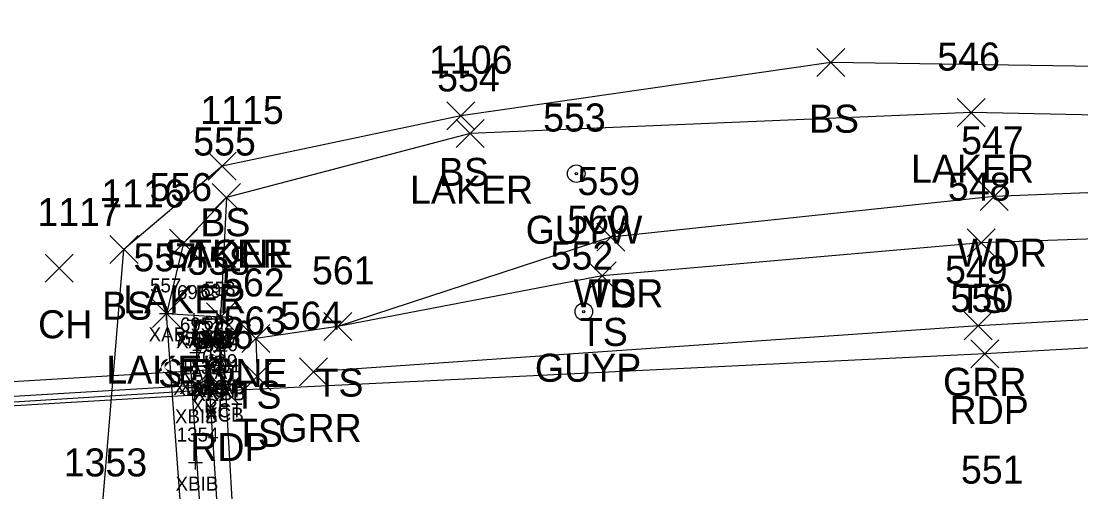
# Model space of a CAD drawing. Extents: x 1715662 to 1717487, y 887396 to 890004.
# Drawn here: x 1717162.5 to 1717238, y 888253.5 to 888287.1 of the extents above; entities that cross this region are included whole.
import ezdxf

# ---------------------------------------------------------------- set-up
doc = ezdxf.new("R2010")
doc.units = 0
for name, color, linetype in [('B_A', 7, 'Continuous'), ('B_I', 7, 'Continuous'), ('B_TIC', 7, 'Continuous'), ('BDC', 7, 'Continuous'), ('BF', 7, 'Continuous'), ('BR', 7, 'Continuous'), ('BSE', 7, 'Continuous'), ('BSUBM', 7, 'Continuous'), ('L_A', 7, 'Continuous'), ('L_I', 7, 'Continuous'), ('L_TIC', 7, 'Continuous'), ('LASF', 7, 'Continuous'), ('LAWA', 7, 'Continuous'), ('LAWE', 7, 'Continuous'), ('LELB', 7, 'Continuous'), ('P_A', 7, 'Continuous'), ('P_I', 7, 'Continuous'), ('P_TIC', 7, 'Continuous'), ('PET', 7, 'Continuous'), ('R_A', 7, 'Continuous'), ('R_I', 7, 'Continuous'), ('R_TIC', 7, 'Continuous'), ('RGR', 7, 'Continuous'), ('U_A', 7, 'Continuous'), ('U_I', 7, 'Continuous'), ('UPGW', 7, 'Continuous')]:
    doc.layers.add(name, color=color, linetype=linetype)

msp = doc.modelspace()

# ---------------------------------------------------------------- linework, layer by layer
at = {"layer": 'B_TIC'}
for p, q in [((1717172.863, 888266.22), (1717172.939, 888266.22)), ((1717174.834, 888265.741), (1717174.91, 888265.741)), ((1717176.473, 888265.837), (1717176.548, 888265.837)), ((1717176.717, 888265.975), (1717176.792, 888265.975)), ((1717175.018, 888263.43), (1717175.094, 888263.43)), ((1717176.687, 888263.555), (1717176.762, 888263.555)), ((1717174.599, 888262.408), (1717174.675, 888262.408)), ((1717175.062, 888262.468), (1717175.137, 888262.468)), ((1717175.803, 888262.49), (1717175.879, 888262.49)), ((1717176.726, 888262.528), (1717176.802, 888262.528)), ((1717177.084, 888262.456), (1717177.16, 888262.456)), ((1717176.001, 888261.982), (1717176.076, 888261.982)), ((1717176.593, 888262.234), (1717176.668, 888262.234)), ((1717176.593, 888262.234), (1717176.668, 888262.234)), ((1717176.979, 888262.024), (1717177.055, 888262.024)), ((1717175.884, 888261.141), (1717175.959, 888261.141)), ((1717174.882, 888260.387), (1717174.958, 888260.387)), ((1717176.87, 888260.514), (1717176.945, 888260.514)), ((1717176.881, 888260.812), (1717176.956, 888260.812)), ((1717174.931, 888255.588), (1717175.006, 888255.588))]:
    msp.add_line(p, q, dxfattribs=at)
for points in [[(1717172.36, 888266.22), (1717173.36, 888266.22)], [(1717172.86, 888265.72), (1717172.86, 888266.72)], [(1717174.831, 888265.241), (1717174.831, 888266.241)], [(1717176.469, 888265.337), (1717176.469, 888266.337)], [(1717176.713, 888265.475), (1717176.713, 888266.475)], [(1717174.331, 888265.741), (1717175.331, 888265.741)], [(1717175.969, 888265.837), (1717176.969, 888265.837)], [(1717176.213, 888265.975), (1717177.213, 888265.975)], [(1717175.015, 888262.93), (1717175.015, 888263.93)], [(1717176.683, 888263.055), (1717176.683, 888264.055)], [(1717174.515, 888263.43), (1717175.515, 888263.43)], [(1717176.183, 888263.555), (1717177.183, 888263.555)], [(1717174.096, 888262.408), (1717175.096, 888262.408)], [(1717174.558, 888262.468), (1717175.558, 888262.468)], [(1717174.596, 888261.908), (1717174.596, 888262.908)], [(1717175.058, 888261.968), (1717175.058, 888262.968)], [(1717175.3, 888262.49), (1717176.3, 888262.49)], [(1717175.8, 888261.99), (1717175.8, 888262.99)], [(1717175.997, 888261.482), (1717175.997, 888262.482)], [(1717176.223, 888262.528), (1717177.223, 888262.528)], [(1717176.581, 888262.456), (1717177.581, 888262.456)], [(1717176.589, 888261.734), (1717176.589, 888262.734)], [(1717176.589, 888261.734), (1717176.589, 888262.734)], [(1717176.723, 888262.028), (1717176.723, 888263.028)], [(1717176.976, 888261.524), (1717176.976, 888262.524)], [(1717177.081, 888261.956), (1717177.081, 888262.956)], [(1717175.497, 888261.982), (1717176.497, 888261.982)], [(1717175.88, 888260.641), (1717175.88, 888261.641)], [(1717176.089, 888262.234), (1717177.089, 888262.234)], [(1717176.089, 888262.234), (1717177.089, 888262.234)], [(1717176.476, 888262.024), (1717177.476, 888262.024)], [(1717174.879, 888259.887), (1717174.879, 888260.887)], [(1717175.38, 888261.141), (1717176.38, 888261.141)], [(1717176.866, 888260.014), (1717176.866, 888261.014)], [(1717176.877, 888260.312), (1717176.877, 888261.312)], [(1717174.379, 888260.387), (1717175.379, 888260.387)], [(1717176.366, 888260.514), (1717177.366, 888260.514)], [(1717176.377, 888260.812), (1717177.377, 888260.812)], [(1717174.427, 888255.588), (1717175.427, 888255.588)], [(1717174.927, 888255.088), (1717174.927, 888256.088)]]:
    msp.add_lwpolyline(points, dxfattribs=at)
at = {"layer": 'BDC'}
for points in [[(1717176.589, 888262.234), (1717176.877, 888260.812), (1717116.829, 888257.088), (1717056.7, 888253.344), (1716997.03, 888249.858), (1716936.998, 888246.313), (1716877.496, 888242.928), (1716877.301, 888244.49)], [(1717176.976, 888262.024), (1717176.866, 888260.514), (1717116.827, 888256.946), (1717056.83, 888253.148), (1716997.002, 888249.663), (1716937.062, 888246.095), (1716877.423, 888242.56)]]:
    msp.add_lwpolyline(points, dxfattribs=at)
at = {"layer": 'BF'}
msp.add_lwpolyline([(1717176.589, 888262.234), (1717116.538, 888258.636), (1717056.61, 888254.944), (1716996.925, 888251.433), (1716937.102, 888247.945), (1716877.301, 888244.49)], dxfattribs=at)
at = {"layer": 'BR'}
msp.add_lwpolyline([(1717175.997, 888261.982), (1717175.88, 888261.141), (1717117.062, 888257.612), (1717056.557, 888253.997), (1716997.021, 888250.409), (1716936.966, 888246.784), (1716878.141, 888243.386), (1716877.962, 888244.411)], dxfattribs=at)
at = {"layer": 'BSE'}
for points in [[(1717175.8, 888262.49), (1717174.596, 888262.408)], [(1717176.7, 888230.2), (1717174.596, 888262.408)], [(1717175.8, 888262.49), (1717177.89, 888230.3)]]:
    msp.add_lwpolyline(points, dxfattribs=at)
at = {"layer": 'BSUBM'}
for points in [[(1717172.86, 888266.22), (1717176.713, 888265.975), (1717177.081, 888262.456)], [(1717175.765, 888226.393), (1717172.86, 888266.22)], [(1717176.683, 888263.555), (1717176.723, 888262.528), (1717175.058, 888262.468), (1717175.015, 888263.43), (1717174.831, 888265.741), (1717176.469, 888265.837)], [(1717176.469, 888265.837), (1717176.683, 888263.555)]]:
    msp.add_lwpolyline(points, dxfattribs=at)
at = {"layer": 'L_TIC'}
for points in [[(1717219.203, 888283.101), (1717221.203, 888285.101)], [(1717221.203, 888283.101), (1717219.203, 888285.101)], [(1717192.827, 888279.308), (1717194.827, 888281.308)], [(1717194.827, 888279.308), (1717192.827, 888281.308)], [(1717229.209, 888279.531), (1717231.209, 888281.531)], [(1717231.209, 888279.531), (1717229.209, 888281.531)], [(1717193.5, 888278.043), (1717195.5, 888280.043)], [(1717195.5, 888278.043), (1717193.5, 888280.043)], [(1717175.82, 888275.721), (1717177.82, 888277.721)], [(1717177.82, 888275.721), (1717175.82, 888277.721)], [(1717176.118, 888273.475), (1717178.118, 888275.475)], [(1717178.118, 888273.475), (1717176.118, 888275.475)], [(1717176.118, 888273.475), (1717178.118, 888275.475)], [(1717178.118, 888273.475), (1717176.118, 888275.475)], [(1717230.85, 888273.551), (1717232.85, 888275.551)], [(1717232.85, 888273.551), (1717230.85, 888275.551)], [(1717173.059, 888270.227), (1717175.059, 888272.227)], [(1717175.059, 888270.227), (1717173.059, 888272.227)], [(1717203.517, 888270.654), (1717205.517, 888272.654)], [(1717205.517, 888270.654), (1717203.517, 888272.654)], [(1717203.517, 888270.654), (1717205.517, 888272.654)], [(1717205.517, 888270.654), (1717203.517, 888272.654)], [(1717229.913, 888270.259), (1717231.913, 888272.259)], [(1717231.913, 888270.259), (1717229.913, 888272.259)], [(1717168.821, 888269.772), (1717170.821, 888271.772)], [(1717170.821, 888269.772), (1717168.821, 888271.772)], [(1717164.209, 888268.447), (1717166.209, 888270.447)], [(1717166.209, 888268.447), (1717164.209, 888270.447)], [(1717202.911, 888267.903), (1717204.911, 888269.903)], [(1717204.911, 888267.903), (1717202.911, 888269.903)], [(1717171.86, 888265.22), (1717173.86, 888267.22)], [(1717173.86, 888265.22), (1717171.86, 888267.22)], [(1717175.713, 888264.975), (1717177.713, 888266.975)], [(1717177.713, 888264.975), (1717175.713, 888266.975)], [(1717184.063, 888264.292), (1717186.063, 888266.292)], [(1717186.063, 888264.292), (1717184.063, 888266.292)], [(1717184.063, 888264.292), (1717186.063, 888266.292)], [(1717186.063, 888264.292), (1717184.063, 888266.292)], [(1717178.223, 888263.43), (1717180.223, 888265.43)], [(1717180.223, 888263.43), (1717178.223, 888265.43)], [(1717178.323, 888260.717), (1717180.323, 888262.717)], [(1717180.323, 888260.717), (1717178.323, 888262.717)]]:
    msp.add_lwpolyline(points, dxfattribs=at)
at = {"layer": 'LASF'}
msp.add_lwpolyline([(1717177.118, 888274.475), (1717176.713, 888265.975)], dxfattribs=at)
at = {"layer": 'LAWA'}
msp.add_lwpolyline([(1717427.067, 888329.961), (1717424.149, 888313.244), (1717417.81, 888299.744), (1717405.976, 888286.015), (1717373.069, 888282.354), (1717318.582, 888277.997), (1717270.109, 888276.059), (1717231.85, 888274.551), (1717204.517, 888271.654)], dxfattribs=at)
at = {"layer": 'LAWE'}
msp.add_lwpolyline([(1717421.683, 888328.919), (1717420.886, 888312.991), (1717415.109, 888301.397), (1717401.413, 888289.205), (1717371.004, 888285.951), (1717321.686, 888282.443), (1717271.809, 888279.668), (1717230.209, 888280.531), (1717194.5, 888279.043), (1717177.118, 888274.475), (1717174.059, 888271.227), (1717172.86, 888266.22)], dxfattribs=at)
at = {"layer": 'LELB'}
for points in [[(1717397.436, 888368.91), (1717401.938, 888364.629), (1717406.066, 888347.478), (1717411.38, 888343.282), (1717409.785, 888309.959), (1717403.016, 888297.908), (1717392.211, 888290.651), (1717353.828, 888286.564), (1717306.03, 888285.644), (1717272.452, 888283.322), (1717220.203, 888284.101), (1717193.827, 888280.308), (1717176.82, 888276.721), (1717169.821, 888270.772)], [(1717414.269, 888287.03), (1717406.988, 888281.7), (1717373.99, 888277.877), (1717318.522, 888275.495), (1717269.658, 888272.606), (1717230.913, 888271.259), (1717203.911, 888268.903), (1717185.063, 888265.292), (1717179.223, 888264.43), (1717179.323, 888261.717)], [(1717204.517, 888271.654), (1717185.063, 888265.292)], [(1717168.218, 888251.599), (1717169.821, 888270.772)]]:
    msp.add_lwpolyline(points, dxfattribs=at)
at = {"layer": 'P_TIC'}
for points in [[(1717230.181, 888262.331), (1717232.181, 888264.331)], [(1717232.181, 888262.331), (1717230.181, 888264.331)], [(1717176.059, 888259.693), (1717178.059, 888261.693)], [(1717178.059, 888259.693), (1717176.059, 888261.693)]]:
    msp.add_lwpolyline(points, dxfattribs=at)
at = {"layer": 'PET'}
msp.add_lwpolyline([(1717427.273, 888275.567), (1717374.238, 888271.922), (1717317.861, 888268.58), (1717269.995, 888265.537), (1717231.181, 888263.331), (1717177.059, 888260.693), (1717177.797, 888248.053), (1717178.6, 888236.513), (1717214.025, 888237.983), (1717254.522, 888239.738), (1717289.284, 888241.313), (1717339.424, 888243.96), (1717387.667, 888246.786), (1717419.304, 888248.633), (1717429.054, 888249.533)], dxfattribs=at)
at = {"layer": 'R_TIC'}
for points in [[(1717229.713, 888264.344), (1717231.713, 888266.344)], [(1717231.713, 888264.344), (1717229.713, 888266.344)], [(1717182.335, 888261.06), (1717184.335, 888263.06)], [(1717184.335, 888261.06), (1717182.335, 888263.06)]]:
    msp.add_lwpolyline(points, dxfattribs=at)
at = {"layer": 'RGR'}
msp.add_lwpolyline([(1717414.455, 888276.435), (1717374.087, 888273.702), (1717318.257, 888270.694), (1717269.907, 888267.54), (1717230.713, 888265.344), (1717183.335, 888262.06)], dxfattribs=at)
at = {"layer": 'UPGW'}
for centre, radius in [((1717202.058, 888276.185), 0.625), ((1717202.058, 888276.185), 0.0833), ((1717202.597, 888266.347), 0.625), ((1717202.597, 888266.347), 0.0833)]:
    msp.add_circle(centre, radius, dxfattribs=at)

# ---------------------------------------------------------------- texts
at = {"layer": 'B_A'}
for s, p in [('XAB', (1717171.58, 888264.22)), ('XAT', (1717173.535, 888263.741)), ('XAT', (1717175.174, 888263.837)), ('XAB', (1717175.434, 888263.975)), ('XAT', (1717173.72, 888261.43)), ('XAT', (1717175.388, 888261.555)), ('XBS', (1717173.336, 888260.408)), ('XAT', (1717173.763, 888260.468)), ('XBS', (1717174.54, 888260.49)), ('XRF', (1717174.757, 888259.982)), ('XFAT', (1717174.845, 888260.234)), ('XCT', (1717175.31, 888260.234)), ('XAT', (1717175.428, 888260.528)), ('XCB', (1717175.712, 888260.024)), ('XAB', (1717175.801, 888260.456)), ('XRF', (1717174.64, 888259.141)), ('XBIB', (1717173.45, 888258.387)), ('XCT', (1717175.598, 888258.812)), ('XCB', (1717175.603, 888258.514)), ('XBIB', (1717173.498, 888253.588))]:
    msp.add_text(s, height=1, dxfattribs=at).set_placement(p)
at = {"layer": 'B_I'}
for s, p in [('557', (1717171.679, 888267.72)), ('558', (1717175.532, 888267.475)), ('696', (1717173.598, 888267.241)), ('697', (1717175.265, 888267.337)), ('695', (1717173.81, 888264.93)), ('692', (1717175.479, 888265.055)), ('759', (1717173.411, 888263.908)), ('694', (1717173.854, 888263.968)), ('1379', (1717174.45, 888263.99)), ('698', (1717175.384, 888263.734)), ('698', (1717175.384, 888263.734)), ('693', (1717175.518, 888264.028)), ('565', (1717175.876, 888263.956)), ('702', (1717174.777, 888263.482)), ('700', (1717175.712, 888263.524)), ('703', (1717174.66, 888262.641)), ('699', (1717175.669, 888262.312)), ('1132', (1717173.816, 888261.887)), ('701', (1717175.929, 888262.014)), ('1354', (1717173.581, 888257.088))]:
    msp.add_text(s, height=1, dxfattribs=at).set_placement(p)
at = {"layer": 'L_A'}
for s, p in [('BS', (1717218.644, 888279.101)), ('LAKER', (1717225.918, 888275.531)), ('BS', (1717192.268, 888275.308)), ('LAKER', (1717190.209, 888274.043)), ('BS', (1717175.261, 888271.721)), ('STONE', (1717172.661, 888269.475)), ('LAKER', (1717172.827, 888269.475)), ('WDR', (1717229.212, 888269.551)), ('WDR', (1717201.879, 888266.654)), ('TS', (1717202.926, 888266.654)), ('BS', (1717168.262, 888265.772)), ('LAKER', (1717169.767, 888266.227)), ('TS', (1717229.323, 888266.259)), ('CH', (1717163.698, 888264.447)), ('TS', (1717202.32, 888263.903)), ('LAKER', (1717168.568, 888261.22)), ('STONE', (1717172.257, 888260.975)), ('TS', (1717183.472, 888260.292)), ('TS', (1717183.472, 888260.292)), ('TS', (1717177.632, 888259.43)), ('TS', (1717177.732, 888256.717))]:
    msp.add_text(s, height=2, dxfattribs=at).set_placement(p)
at = {"layer": 'L_I'}
for s, p in [('1106', (1717191.567, 888283.308)), ('546', (1717227.792, 888283.531)), ('554', (1717192.138, 888282.043)), ('1115', (1717175.261, 888279.721)), ('555', (1717174.756, 888277.475)), ('555', (1717174.756, 888277.475)), ('547', (1717229.487, 888277.551)), ('556', (1717171.641, 888274.227)), ('559', (1717202.147, 888274.654)), ('559', (1717202.147, 888274.654)), ('548', (1717228.551, 888274.259)), ('1116', (1717168.206, 888273.772)), ('1117', (1717163.65, 888272.447)), ('560', (1717201.415, 888271.903)), ('557', (1717170.498, 888269.22)), ('558', (1717174.351, 888268.975)), ('561', (1717183.22, 888268.292)), ('561', (1717183.22, 888268.292)), ('562', (1717176.813, 888267.43)), ('563', (1717176.913, 888264.717)), ('1353', (1717165.525, 888254.599))]:
    msp.add_text(s, height=2, dxfattribs=at).set_placement(p)
at = {"layer": 'P_A'}
for p in [(1717228.669, 888258.331), (1717174.547, 888255.693)]:
    msp.add_text('RDP', height=2, dxfattribs=at).set_placement(p)
at = {"layer": 'P_I'}
for s, p in [('550', (1717228.732, 888266.331)), ('566', (1717174.594, 888263.693)), ('551', (1717229.476, 888254.088))]:
    msp.add_text(s, height=2, dxfattribs=at).set_placement(p)
at = {"layer": 'R_A'}
for p in [(1717228.201, 888260.344), (1717180.823, 888257.06)]:
    msp.add_text('GRR', height=2, dxfattribs=at).set_placement(p)
at = {"layer": 'R_I'}
for s, p in [('549', (1717228.343, 888268.344)), ('564', (1717180.925, 888265.06))]:
    msp.add_text(s, height=2, dxfattribs=at).set_placement(p)
at = {"layer": 'U_A'}
for s, p in [('GUYW', (1717198.452, 888271.185)), ('GUYP', (1717199.109, 888261.347))]:
    msp.add_text(s, height=2, dxfattribs=at).set_placement(p)
at = {"layer": 'U_I'}
for s, p in [('553', (1717199.696, 888279.185)), ('552', (1717200.235, 888269.347))]:
    msp.add_text(s, height=2, dxfattribs=at).set_placement(p)

doc.saveas('drawing.dxf')
